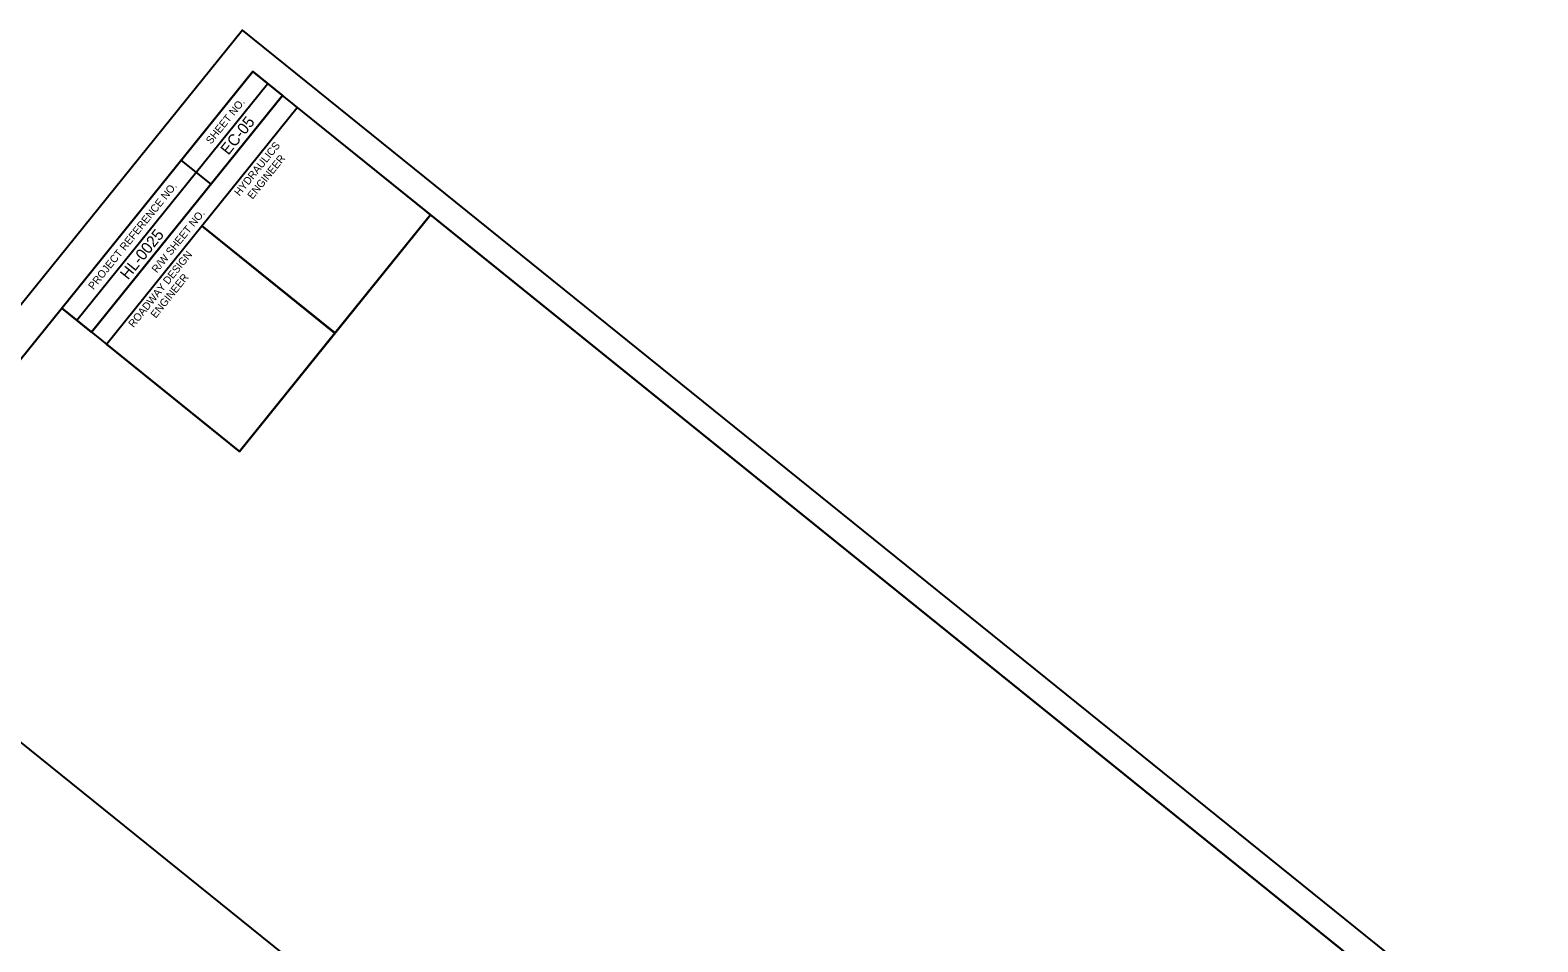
# Model space of a CAD drawing. Extents: x 1487432 to 1489935, y 497862 to 500368.
# Drawn here: x 1488762 to 1489754, y 499768 to 500368 of the extents above; entities that cross this region are included whole.
import ezdxf

# ---------------------------------------------------------------- set-up
doc = ezdxf.new("R2010")
doc.units = 0
for name, color, linetype in [('Level 10', 7, 'Continuous'), ('Level 19', 7, 'Continuous'), ('Level 2', 7, 'Continuous'), ('Level 3', 7, 'Continuous'), ('Level 5', 7, 'Continuous')]:
    doc.layers.add(name, color=color, linetype=linetype)

msp = doc.modelspace()

# ---------------------------------------------------------------- linework, layer by layer
at = {"layer": 'Level 10'}
msp.add_lwpolyline([(1488182.96, 499420.46), (1488642.29, 499990.04), (1489445.19, 499342.54), (1488985.86, 498772.96)], close=True, dxfattribs=at)
at = {"layer": 'Level 19'}
for p, q in [((1488792.49, 500176.83), (1488918.08, 500332.55)), ((1488802.25, 500168.97), (1488927.81, 500324.7)), ((1488802.25, 500168.97), (1488927.81, 500324.7)), ((1488861.26, 500281.99), (1488880.75, 500266.33)), ((1488874.78, 500239.01), (1488962.33, 500168.43)), ((1488802.25, 500168.97), (1488811.97, 500161.13))]:
    msp.add_line(p, q, dxfattribs=at)
for points in [[(1488908.33, 500340.46), (1487966.68, 499172.8), (1488784.02, 498513.67), (1489725.65, 499681.3)], [(1488782.72, 500184.72), (1488908.33, 500340.46), (1488927.81, 500324.7), (1488802.25, 500168.97)], [(1488874.78, 500239.01), (1488937.54, 500316.85), (1489025.13, 500246.23), (1488962.36, 500168.38)], [(1488784.02, 498513.67), (1487966.69, 499172.77), (1488782.72, 500184.72), (1488899.54, 500090.53), (1489025.13, 500246.23), (1489725.65, 499681.3)], [(1488811.97, 500161.13), (1488874.78, 500239.01), (1488962.36, 500168.38), (1488899.54, 500090.53)]]:
    msp.add_lwpolyline(points, close=True, dxfattribs=at)
at = {"layer": 'Level 2'}
msp.add_line((1488802.23, 500168.98), (1488811.96, 500161.13), dxfattribs=at)
at = {"layer": 'Level 5'}
msp.add_lwpolyline([(1488697.03, 498369.94), (1489753.85, 499680.4), (1488901.48, 500367.79), (1487844.66, 499057.32)], close=True, dxfattribs=at)

# ---------------------------------------------------------------- texts
at = {"layer": 'Level 19'}
for s, height, p in [('SHEET NO.', 5, (1488880.85, 500292.33)), ('HYDRAULICS', 5, (1488899.57, 500258.16)), ('ENGINEER', 5, (1488908.13, 500256.09)), ('PROJECT REFERENCE NO.', 5.0001, (1488803.45, 500196.53)), ('R/W SHEET NO.', 5.0001, (1488845.19, 500207.58)), ('ROADWAY DESIGN', 5.0001, (1488829.82, 500171.63)), ('ENGINEER', 5, (1488844.47, 500177.79))]:
    msp.add_text(s, height=height, rotation=51.11565, dxfattribs=at).set_placement(p)
at = {"layer": 'Level 3'}
for s, p in [('EC-05', (1488892.25, 500285.07)), ('HL-0025', (1488826.16, 500203.02))]:
    msp.add_text(s, height=7.5, rotation=51.11565, dxfattribs=at).set_placement(p)

doc.saveas('drawing.dxf')
